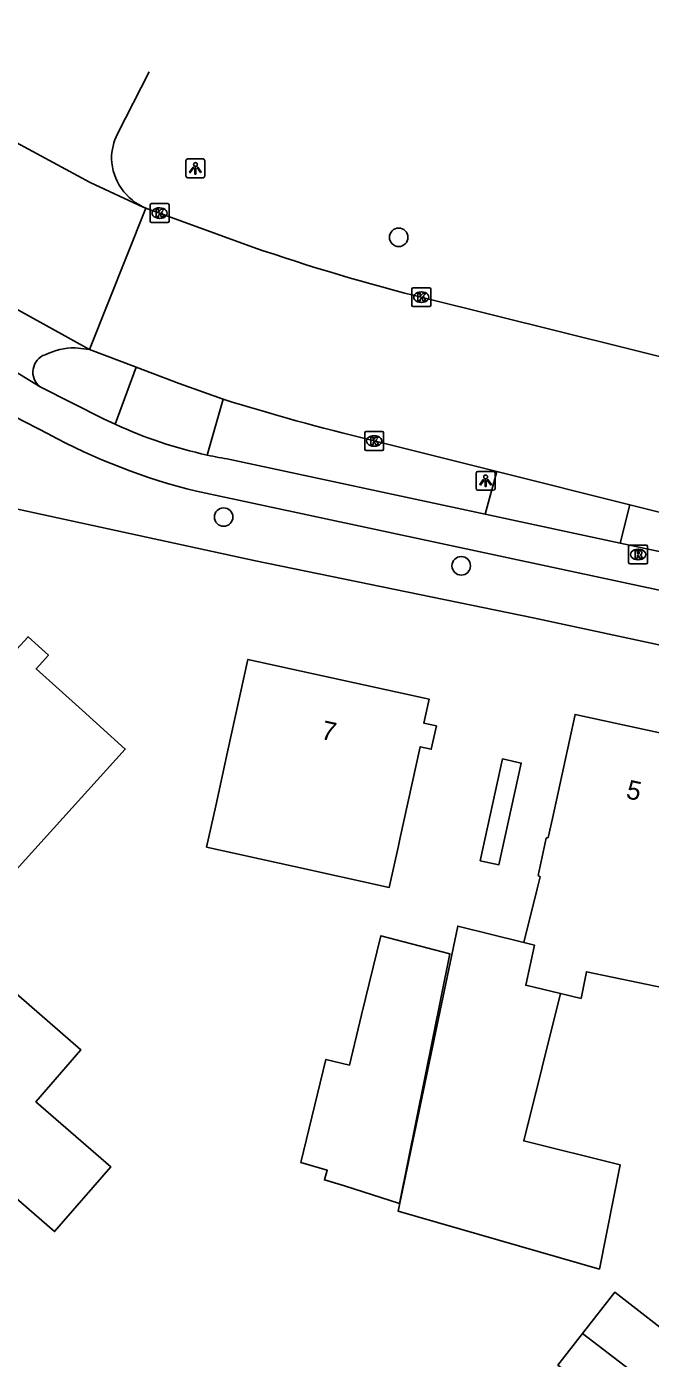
# Model space of a CAD drawing. Extents: x 160026 to 161302, y 384757 to 385701.
# Drawn here: x 160583.2 to 160616.2, y 385295.1 to 385365.6 of the extents above; entities that cross this region are included whole.
import ezdxf

# ---------------------------------------------------------------- set-up
doc = ezdxf.new("R2010")
doc.units = 0
for name, color, linetype in [('IMGEO_Boom', 7, 'Continuous'), ('IMGEO_Fietspad_gesloten', 7, 'Continuous'), ('IMGEO_Kolk', 7, 'Continuous'), ('IMGEO_Lichtpunt', 7, 'Continuous'), ('IMGEO_Pand', 7, 'Continuous'), ('IMGEO_Pand_nummerreeks', 7, 'Continuous'), ('IMGEO_Pand_vergunning_verleend', 7, 'Continuous'), ('IMGEO_Rijbaan_lokaal_gesloten', 7, 'Continuous'), ('IMGEO_Rijbaan_lokaal_open', 7, 'Continuous'), ('IMGEO_Rioolput', 7, 'Continuous'), ('IMGEO_Voetpad_open', 7, 'Continuous')]:
    doc.layers.add(name, color=color, linetype=linetype)

msp = doc.modelspace()

# ---------------------------------------------------------------- linework, layer by layer
at = {"layer": 'IMGEO_Boom'}
for centre in [(160602.881, 385354.415), (160593.626, 385339.613), (160606.187, 385337.033)]:
    msp.add_circle(centre, 0.489, dxfattribs=at)
at = {"layer": 'IMGEO_Fietspad_gesloten'}
for points in [[(160583.924, 385346.505), (160587.309, 385344.801), (160587.9, 385344.519)], [(160582.568, 385344.935), (160584.353, 385344.018)], [(160593.971, 385342.659), (160607.458, 385339.768)], [(160592.186, 385340.982), (160649.272, 385328.76), (160651.523, 385328.278)], [(160614.596, 385338.238), (160607.458, 385339.768)], [(160614.596, 385338.238), (160628.49, 385335.26)]]:
    msp.add_lwpolyline(points, dxfattribs=at)
for centre, radius, start, end in [((160599.827, 385372.32), 32.256, 241.33182, 256.29641), ((160597.887, 385366.283), 23.946, 245.35007, 257.63865), ((160598.116, 385367.445), 25.13, 257.69556, 260.50529)]:
    msp.add_arc(centre, radius, start, end, dxfattribs=at)
at = {"layer": 'IMGEO_Kolk'}
for p, q in [((160589.744, 385355.269), (160589.744, 385356.121)), ((160589.819, 385356.195), (160590.671, 385356.195)), ((160590.232, 385355.975), (160590.257, 385355.975)), ((160590.745, 385356.121), (160590.745, 385355.269)), ((160590.671, 385355.195), (160589.819, 385355.195)), ((160590.255, 385355.415), (160590.23, 385355.415)), ((160603.575, 385350.823), (160603.575, 385351.675)), ((160603.65, 385351.749), (160604.502, 385351.749)), ((160604.576, 385351.675), (160604.576, 385350.823)), ((160604.086, 385350.969), (160604.061, 385350.969)), ((160604.063, 385351.529), (160604.088, 385351.529)), ((160604.502, 385350.749), (160603.65, 385350.749)), ((160601.083, 385343.212), (160601.083, 385344.064)), ((160601.158, 385344.138), (160602.01, 385344.138)), ((160601.571, 385343.918), (160601.596, 385343.918)), ((160602.084, 385344.064), (160602.084, 385343.212)), ((160601.594, 385343.358), (160601.569, 385343.358)), ((160602.01, 385343.138), (160601.158, 385343.138))]:
    msp.add_line(p, q, dxfattribs=at)
for points in [[(160589.744, 385355.269), (160589.744, 385356.121)], [(160589.819, 385356.195), (160590.671, 385356.195)], [(160590.065, 385355.895), (160590.188, 385355.895), (160590.188, 385355.744), (160590.318, 385355.895), (160590.482, 385355.895), (160590.336, 385355.744), (160590.489, 385355.495), (160590.337, 385355.495), (160590.252, 385355.659), (160590.188, 385355.592), (160590.188, 385355.495), (160590.065, 385355.495), (160590.065, 385355.895)], [(160590.745, 385356.121), (160590.745, 385355.269)], [(160590.671, 385355.195), (160589.819, 385355.195)], [(160603.575, 385350.823), (160603.575, 385351.675)], [(160603.65, 385351.749), (160604.502, 385351.749)], [(160604.576, 385351.675), (160604.576, 385350.823)], [(160603.896, 385351.449), (160604.019, 385351.449), (160604.019, 385351.298), (160604.149, 385351.449), (160604.313, 385351.449), (160604.167, 385351.298), (160604.32, 385351.049), (160604.168, 385351.049), (160604.083, 385351.213), (160604.019, 385351.146), (160604.019, 385351.049), (160603.896, 385351.049), (160603.896, 385351.449)], [(160604.502, 385350.749), (160603.65, 385350.749)], [(160601.083, 385343.212), (160601.083, 385344.064)], [(160601.158, 385344.138), (160602.01, 385344.138)], [(160602.084, 385344.064), (160602.084, 385343.212)], [(160601.404, 385343.838), (160601.527, 385343.838), (160601.527, 385343.687), (160601.657, 385343.838), (160601.821, 385343.838), (160601.675, 385343.687), (160601.828, 385343.438), (160601.676, 385343.438), (160601.591, 385343.602), (160601.527, 385343.535), (160601.527, 385343.438), (160601.404, 385343.438), (160601.404, 385343.838)], [(160602.01, 385343.138), (160601.158, 385343.138)]]:
    msp.add_lwpolyline(points, dxfattribs=at)
for centre, start, end in [((160589.821, 385356.119), 91.55205, 178.44795), ((160589.821, 385356.119), 91.55205, 178.44795), ((160590.669, 385356.119), 1.55205, 88.44795), ((160590.669, 385356.119), 1.55205, 88.44795), ((160589.821, 385355.271), 181.55205, 268.44795), ((160589.821, 385355.271), 181.55205, 268.44795), ((160590.669, 385355.271), 271.55205, 358.44795), ((160590.669, 385355.271), 271.55205, 358.44795), ((160603.652, 385351.673), 91.55205, 178.44795), ((160603.652, 385351.673), 91.55205, 178.44795), ((160604.5, 385351.673), 1.55205, 88.44795), ((160604.5, 385351.673), 1.55205, 88.44795), ((160603.652, 385350.825), 181.55205, 268.44795), ((160603.652, 385350.825), 181.55205, 268.44795), ((160604.5, 385350.825), 271.55205, 358.44795), ((160604.5, 385350.825), 271.55205, 358.44795), ((160601.16, 385344.062), 91.55205, 178.44795), ((160601.16, 385344.062), 91.55205, 178.44795), ((160602.008, 385344.062), 1.55205, 88.44795), ((160602.008, 385344.062), 1.55205, 88.44795), ((160601.16, 385343.214), 181.55205, 268.44795), ((160601.16, 385343.214), 181.55205, 268.44795), ((160602.008, 385343.214), 271.55205, 358.44795), ((160602.008, 385343.214), 271.55205, 358.44795)]:
    msp.add_arc(centre, 0.0765, start, end, dxfattribs=at)
for centre, major_axis, ratio, start_param, end_param in [((160590.231, 385355.695), (-0.387, 0.002), 0.722429, 4.712389, 7.853982), ((160590.256, 385355.695), (-0.39, 0.002), 0.717154, 1.570796, 4.712389), ((160604.062, 385351.249), (-0.387, 0.002), 0.722429, 4.712389, 7.853982), ((160604.087, 385351.249), (-0.39, 0.002), 0.717154, 1.570796, 4.712389), ((160601.57, 385343.638), (-0.387, 0.002), 0.722429, 4.712389, 7.853982), ((160601.595, 385343.638), (-0.39, 0.002), 0.717154, 1.570796, 4.712389)]:
    msp.add_ellipse(centre, major_axis=major_axis, ratio=ratio, start_param=start_param, end_param=end_param, dxfattribs=at)
at = {"layer": 'IMGEO_Lichtpunt'}
for p, q in [((160591.637, 385358.468), (160591.637, 385357.661)), ((160591.637, 385358.468), (160591.637, 385357.661)), ((160592.539, 385358.563), (160591.731, 385358.563)), ((160592.539, 385358.563), (160591.731, 385358.563)), ((160592.633, 385357.661), (160592.633, 385358.468)), ((160592.633, 385357.661), (160592.633, 385358.468)), ((160591.731, 385357.567), (160592.539, 385357.567)), ((160591.731, 385357.567), (160592.539, 385357.567)), ((160606.977, 385341.935), (160606.977, 385341.128)), ((160606.977, 385341.935), (160606.977, 385341.128)), ((160607.879, 385342.03), (160607.071, 385342.03)), ((160607.879, 385342.03), (160607.071, 385342.03)), ((160607.973, 385341.128), (160607.973, 385341.935)), ((160607.973, 385341.128), (160607.973, 385341.935)), ((160607.071, 385341.034), (160607.879, 385341.034)), ((160607.071, 385341.034), (160607.879, 385341.034))]:
    msp.add_line(p, q, dxfattribs=at)
for points in [[(160592.011, 385358.132), (160592.05, 385358.104), (160591.862, 385357.842), (160591.824, 385357.869), (160592.011, 385358.132)], [(160592.113, 385358.084), (160592.16, 385358.084), (160592.16, 385357.762), (160592.113, 385357.762), (160592.113, 385358.084)], [(160592.223, 385358.104), (160592.261, 385358.131), (160592.448, 385357.869), (160592.409, 385357.841), (160592.223, 385358.104)], [(160607.351, 385341.599), (160607.39, 385341.571), (160607.202, 385341.309), (160607.164, 385341.336), (160607.351, 385341.599)], [(160607.453, 385341.551), (160607.5, 385341.551), (160607.5, 385341.229), (160607.453, 385341.229), (160607.453, 385341.551)], [(160607.563, 385341.571), (160607.601, 385341.598), (160607.788, 385341.336), (160607.749, 385341.308), (160607.563, 385341.571)]]:
    msp.add_lwpolyline(points, dxfattribs=at)
for centre in [(160592.136, 385358.266), (160607.476, 385341.733)]:
    msp.add_circle(centre, 0.0994, dxfattribs=at)
for centre, start, end in [((160591.731, 385358.468), 90, 180), ((160591.731, 385358.468), 90, 180), ((160592.539, 385358.468), 0, 90), ((160592.539, 385358.468), 0, 90), ((160591.731, 385357.661), 180, 270), ((160591.731, 385357.661), 180, 270), ((160592.539, 385357.661), 270, 0), ((160592.539, 385357.661), 270, 360), ((160607.071, 385341.935), 90, 180), ((160607.071, 385341.935), 90, 180), ((160607.879, 385341.935), 0, 90), ((160607.879, 385341.935), 0, 90), ((160607.071, 385341.128), 180, 270), ((160607.071, 385341.128), 180, 270), ((160607.879, 385341.128), 270, 0), ((160607.879, 385341.128), 270, 360)]:
    msp.add_arc(centre, 0.0946, start, end, dxfattribs=at)
at = {"layer": 'IMGEO_Pand'}
for points in [[(160577.566, 385319.909), (160579.844, 385317.849), (160588.423, 385327.334), (160586.145, 385329.394), (160583.716, 385331.591), (160584.369, 385332.313), (160583.295, 385333.284), (160582.675, 385332.598), (160579.301, 385335.649), (160570.69, 385326.128), (160574.398, 385322.774), (160577.566, 385319.909)], [(160592.726, 385322.142), (160593.209, 385324.339), (160593.838, 385327.199), (160594.912, 385332.082), (160604.485, 385329.976), (160604.207, 385328.71), (160604.877, 385328.562), (160604.605, 385327.329), (160604.023, 385327.457), (160602.948, 385322.574), (160602.869, 385322.213), (160602.385, 385320.016), (160597.291, 385321.137), (160592.726, 385322.142)], [(160609.491, 385317.101), (160610.192, 385319.936), (160610.351, 385320.58), (160610.248, 385320.649), (160610.678, 385322.627), (160610.788, 385322.662), (160611.007, 385323.668), (160612.206, 385329.172), (160618.558, 385327.788), (160619.672, 385327.545), (160619.57, 385327.077)], [(160607.183, 385321.432), (160608.178, 385321.213), (160609.363, 385326.599), (160608.369, 385326.818), (160607.183, 385321.432)], [(160611.433, 385314.401), (160609.493, 385306.609), (160614.591, 385305.339), (160613.488, 385299.823), (160602.854, 385302.887), (160606.005, 385317.969), (160609.491, 385317.101)], [(160609.491, 385317.101), (160610.063, 385316.959), (160609.601, 385314.838), (160611.433, 385314.401)], [(160617.249, 385316.422), (160616.874, 385314.698), (160612.802, 385315.558), (160612.519, 385314.142), (160611.433, 385314.401)], [(160581.698, 385315.228), (160586.085, 385311.418), (160583.703, 385308.676), (160587.666, 385305.233), (160584.69, 385301.807), (160578.624, 385307.076)], [(160630.142, 385289.849), (160626.197, 385292.921), (160623.496, 385295.023), (160621.759, 385292.793), (160614.303, 385298.6), (160612.6, 385296.413)], [(160612.6, 385296.413), (160611.294, 385294.736), (160618.633, 385289.02), (160616.963, 385286.877), (160619.834, 385284.643), (160623.779, 385281.571)], [(160612.6, 385296.413), (160615.912, 385293.869), (160616.065, 385294.068), (160618.442, 385292.242), (160618.537, 385292.366), (160627.05, 385285.827)]]:
    msp.add_lwpolyline(points, dxfattribs=at)
at = {"layer": 'IMGEO_Pand_vergunning_verleend'}
msp.add_lwpolyline([(160602.916, 385303.286), (160600.018, 385304.224), (160598.955, 385304.541), (160599.108, 385305.054), (160597.714, 385305.47), (160599.038, 385310.915), (160600.274, 385310.615), (160600.922, 385313.281), (160601.938, 385317.456), (160605.579, 385316.506), (160602.916, 385303.286)], dxfattribs=at)
at = {"layer": 'IMGEO_Rijbaan_lokaal_gesloten'}
for points in [[(160574.382, 385365.561), (160578.304, 385362.312), (160582.66, 385359.423), (160586.575, 385357.322), (160589.368, 385356.017), (160589.52, 385355.963)], [(160588.012, 385359.887), (160589.689, 385363.171)], [(160586.539, 385348.485), (160589.52, 385355.963)], [(160589.52, 385355.963), (160595.162, 385353.895)], [(160578.824, 385352.749), (160586.539, 385348.485)], [(160604.286, 385351.187), (160650.462, 385339.7)], [(160586.539, 385348.485), (160588.911, 385347.587), (160589.008, 385347.55)], [(160589.008, 385347.55), (160591.268, 385346.683), (160593.605, 385345.843)], [(160601.365, 385343.698), (160608.066, 385342.028)], [(160608.066, 385342.028), (160615.103, 385340.261)], [(160615.103, 385340.261), (160628.825, 385336.823)]]:
    msp.add_lwpolyline(points, dxfattribs=at)
for centre, radius, start, end in [((160590.673, 385358.566), 2.971, 153.59236, 180.10957), ((160590.608, 385358.66), 2.908, 181.96431, 248.02269), ((160631.531, 385459.707), 111.887, 251.03154, 255.90672), ((160633.07, 385473.508), 133.625, 252.82196, 256.27458)]:
    msp.add_arc(centre, radius, start, end, dxfattribs=at)
at = {"layer": 'IMGEO_Rijbaan_lokaal_open'}
for points in [[(160583.924, 385346.505), (160577.22, 385350.613)], [(160586.539, 385348.485), (160585.774, 385348.572)]]:
    msp.add_lwpolyline(points, dxfattribs=at)
for centre, radius, start, end in [((160584.523, 385347.28), 0.979, 109.1739, 232.31707), ((160585.842, 385344.726), 3.846, 91.01189, 115.25385)]:
    msp.add_arc(centre, radius, start, end, dxfattribs=at)
at = {"layer": 'IMGEO_Rioolput'}
for p, q in [((160615.036, 385337.206), (160615.036, 385338.058)), ((160615.111, 385338.132), (160615.963, 385338.132)), ((160615.524, 385337.912), (160615.549, 385337.912)), ((160616.037, 385338.058), (160616.037, 385337.206)), ((160615.963, 385337.132), (160615.111, 385337.132)), ((160615.547, 385337.352), (160615.522, 385337.352))]:
    msp.add_line(p, q, dxfattribs=at)
for points in [[(160615.036, 385337.206), (160615.036, 385338.058)], [(160615.111, 385338.132), (160615.963, 385338.132)], [(160615.625, 385337.83), (160615.373, 385337.832), (160615.373, 385337.432)], [(160615.373, 385337.432), (160615.497, 385337.432), (160615.497, 385337.594), (160615.508, 385337.594)], [(160615.551, 385337.751), (160615.497, 385337.751), (160615.497, 385337.67)], [(160615.497, 385337.67), (160615.549, 385337.67)], [(160615.555, 385337.565), (160615.626, 385337.432), (160615.766, 385337.432), (160615.701, 385337.558)], [(160616.037, 385338.058), (160616.037, 385337.206)], [(160615.963, 385337.132), (160615.111, 385337.132)]]:
    msp.add_lwpolyline(points, dxfattribs=at)
for centre, radius, start, end in [((160615.113, 385338.056), 0.0765, 91.55205, 178.44795), ((160615.113, 385338.056), 0.0765, 91.55205, 178.44795), ((160615.507, 385337.541), 0.0533, 26.02933, 88.69889), ((160615.533, 385337.859), 0.19, 274.7715, 282.96867), ((160615.557, 385337.655), 0.0964, 77.00612, 93.18647), ((160615.571, 385337.712), 0.0378, 276.66336, 79.67722), ((160615.624, 385337.72), 0.109, 350.36119, 89.41601), ((160615.622, 385337.72), 0.112, 277.58423, 350.98172), ((160615.606, 385337.505), 0.108, 29.51342, 73.79051), ((160615.961, 385338.056), 0.0765, 1.55205, 88.44795), ((160615.961, 385338.056), 0.0765, 1.55205, 88.44795), ((160615.113, 385337.208), 0.0765, 181.55205, 268.44795), ((160615.113, 385337.208), 0.0765, 181.55205, 268.44795), ((160615.961, 385337.208), 0.0765, 271.55205, 358.44795), ((160615.961, 385337.208), 0.0765, 271.55205, 358.44795)]:
    msp.add_arc(centre, radius, start, end, dxfattribs=at)
for centre, major_axis, ratio, start_param, end_param in [((160615.523, 385337.632), (-0.387, 0.002), 0.722429, 4.712389, 7.853982), ((160615.548, 385337.632), (-0.39, 0.002), 0.717154, 1.570796, 4.712389)]:
    msp.add_ellipse(centre, major_axis=major_axis, ratio=ratio, start_param=start_param, end_param=end_param, dxfattribs=at)
at = {"layer": 'IMGEO_Voetpad_open'}
for points in [[(160587.9, 385344.519), (160589.008, 385347.55)], [(160593.605, 385345.843), (160592.761, 385342.892)], [(160607.458, 385339.768), (160608.066, 385342.028)], [(160648.878, 385325.926), (160609.984, 385334.289), (160595.313, 385337.293), (160577.45, 385341.176)], [(160615.103, 385340.261), (160614.596, 385338.238)]]:
    msp.add_lwpolyline(points, dxfattribs=at)

# ---------------------------------------------------------------- texts
at = {"layer": 'IMGEO_Pand_nummerreeks'}
for s, rotation, p in [('7', 347.59546, (160598.725, 385327.885)), ('5', 347.71578, (160614.854, 385324.747))]:
    msp.add_text(s, height=1, rotation=rotation, dxfattribs=at).set_placement(p)

doc.saveas('drawing.dxf')
